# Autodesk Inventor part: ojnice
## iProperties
Shininess: 64.0
Length Units: 11269
Angle Units: 11279
Time Units: 11290
Mass Units: 11283
Length Display Precision: 3
Angle Display Precision: 2
Compacted: True
Part Number: ojnice
Document SubType Name: Modeling
Created: 2003-06
Material: Výchozí
Designer: rudolf_martonka
Density: 0.0
Volumn: 0.0
Area: 0.0
PropertySet Name: Model Information
Control State: 0
Master: False
Checked Out: False
Title: ojnice
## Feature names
1. Vysunutí1 [Extrusion]
